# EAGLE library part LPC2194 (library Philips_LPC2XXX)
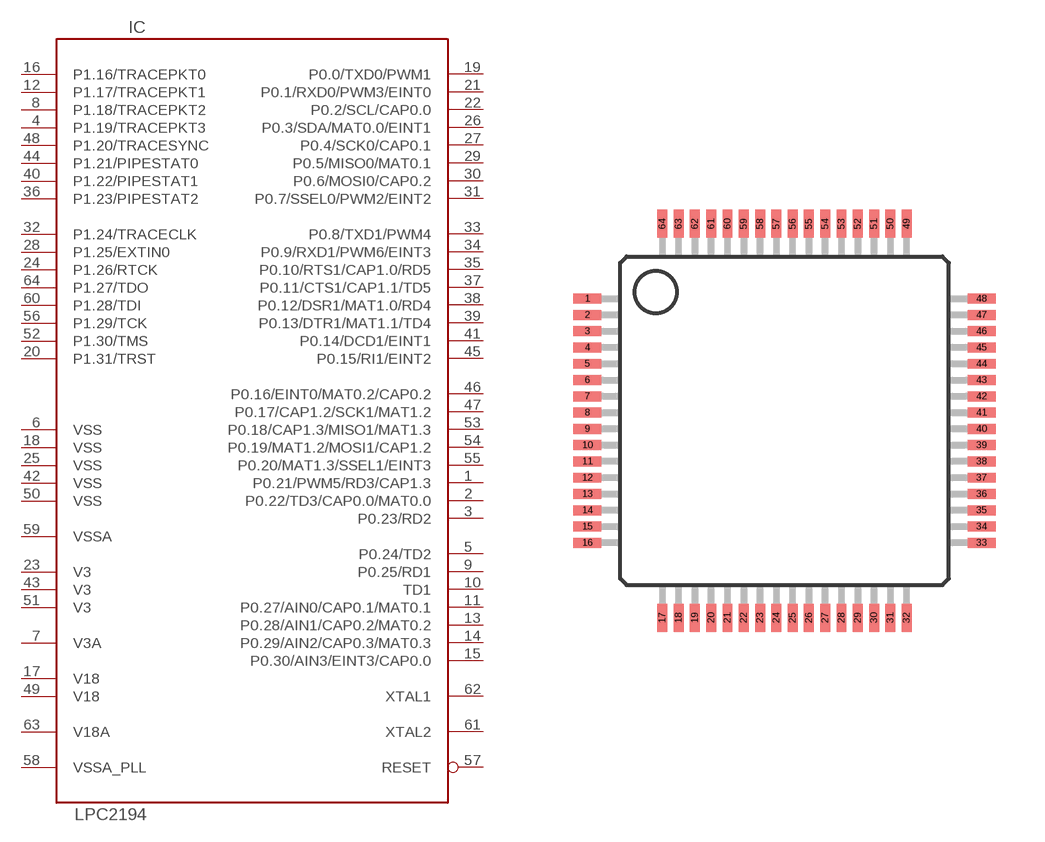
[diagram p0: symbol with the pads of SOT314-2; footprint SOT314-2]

Designator prefix IC

## LPC2194  [SOT314-2]
1  P0.21/PWM5/RD3/CAP1.3
2  P0.22/TD3/CAP0.0/MAT0.0
3  P0.23/RD2
4  P1.19/TRACEPKT3
5  P0.24/TD2
6  VSS  pwr
7  V3A  pwr
8  P1.18/TRACEPKT2
9  P0.25/RD1
10  TD1
11  P0.27/AIN0/CAP0.1/MAT0.1
12  P1.17/TRACEPKT1
13  P0.28/AIN1/CAP0.2/MAT0.2
14  P0.29/AIN2/CAP0.3/MAT0.3
15  P0.30/AIN3/EINT3/CAP0.0
16  P1.16/TRACEPKT0
17  V18  pwr
18  VSS  pwr
19  P0.0/TXD0/PWM1
20  P1.31/TRST
21  P0.1/RXD0/PWM3/EINT0
22  P0.2/SCL/CAP0.0
23  V3  pwr
24  P1.26/RTCK
25  VSS  pwr
26  P0.3/SDA/MAT0.0/EINT1
27  P0.4/SCK0/CAP0.1
28  P1.25/EXTIN0
29  P0.5/MISO0/MAT0.1
30  P0.6/MOSI0/CAP0.2
31  P0.7/SSEL0/PWM2/EINT2
32  P1.24/TRACECLK
33  P0.8/TXD1/PWM4
34  P0.9/RXD1/PWM6/EINT3
35  P0.10/RTS1/CAP1.0/RD5
36  P1.23/PIPESTAT2
37  P0.11/CTS1/CAP1.1/TD5
38  P0.12/DSR1/MAT1.0/RD4
39  P0.13/DTR1/MAT1.1/TD4
40  P1.22/PIPESTAT1
41  P0.14/DCD1/EINT1
42  VSS  pwr
43  V3  pwr
44  P1.21/PIPESTAT0
45  P0.15/RI1/EINT2
46  P0.16/EINT0/MAT0.2/CAP0.2
47  P0.17/CAP1.2/SCK1/MAT1.2
48  P1.20/TRACESYNC
49  V18  pwr
50  VSS  pwr
51  V3  pwr
52  P1.30/TMS
53  P0.18/CAP1.3/MISO1/MAT1.3
54  P0.19/MAT1.2/MOSI1/CAP1.2
55  P0.20/MAT1.3/SSEL1/EINT3
56  P1.29/TCK
57  RESET
58  VSSA_PLL  pwr
59  VSSA  pwr
60  P1.28/TDI
61  XTAL2
62  XTAL1
63  V18A  pwr
64  P1.27/TDO

## Footprint SOT314-2 (pad centres in mm)
smd 0.864 x 0.305: 1 -6.1,3.6; 2 -6.1,3.1; 3 -6.1,2.6; 4 -6.1,2.1; 5 -6.1,1.6; 6 -6.1,1.1; 7 -6.1,0.6; 8 -6.1,0.1; 9 -6.1,-0.4; 10 -6.1,-0.9; 11 -6.1,-1.4; 12 -6.1,-1.9; 13 -6.1,-2.4; 14 -6.1,-2.9; 15 -6.1,-3.4; 16 -6.1,-3.9; 33 6,-3.9; 34 6,-3.4; 35 6,-2.9; 36 6,-2.4; 37 6,-1.9; 38 6,-1.4; 39 6,-0.9; 40 6,-0.4; 41 6,0.1; 42 6,0.6; 43 6,1.1; 44 6,1.6; 45 6,2.1; 46 6,2.6; 47 6,3.1; 48 6,3.6
smd 0.305 x 0.864: 17 -3.8,-6.2; 18 -3.3,-6.2; 19 -2.8,-6.2; 20 -2.3,-6.2; 21 -1.8,-6.2; 22 -1.3,-6.2; 23 -0.8,-6.2; 24 -0.3,-6.2; 25 0.2,-6.2; 26 0.7,-6.2; 27 1.2,-6.2; 28 1.7,-6.2; 29 2.2,-6.2; 30 2.7,-6.2; 31 3.2,-6.2; 32 3.7,-6.2; 49 3.7,5.9; 50 3.2,5.9; 51 2.7,5.9; 52 2.2,5.9; 53 1.7,5.9; 54 1.2,5.9; 55 0.7,5.9; 56 0.2,5.9; 57 -0.3,5.9; 58 -0.8,5.9; 59 -1.3,5.9; 60 -1.8,5.9; 61 -2.3,5.9; 62 -2.8,5.9; 63 -3.3,5.9; 64 -3.8,5.9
